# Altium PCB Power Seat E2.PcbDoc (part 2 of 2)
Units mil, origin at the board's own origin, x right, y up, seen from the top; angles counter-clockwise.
Board outline 6560 x 2560 mil, 2 copper layers (Top Layer, Bottom Layer), stack 61.4 mil thick; 98 components, 83 nets, 370 pads, 533 vias.
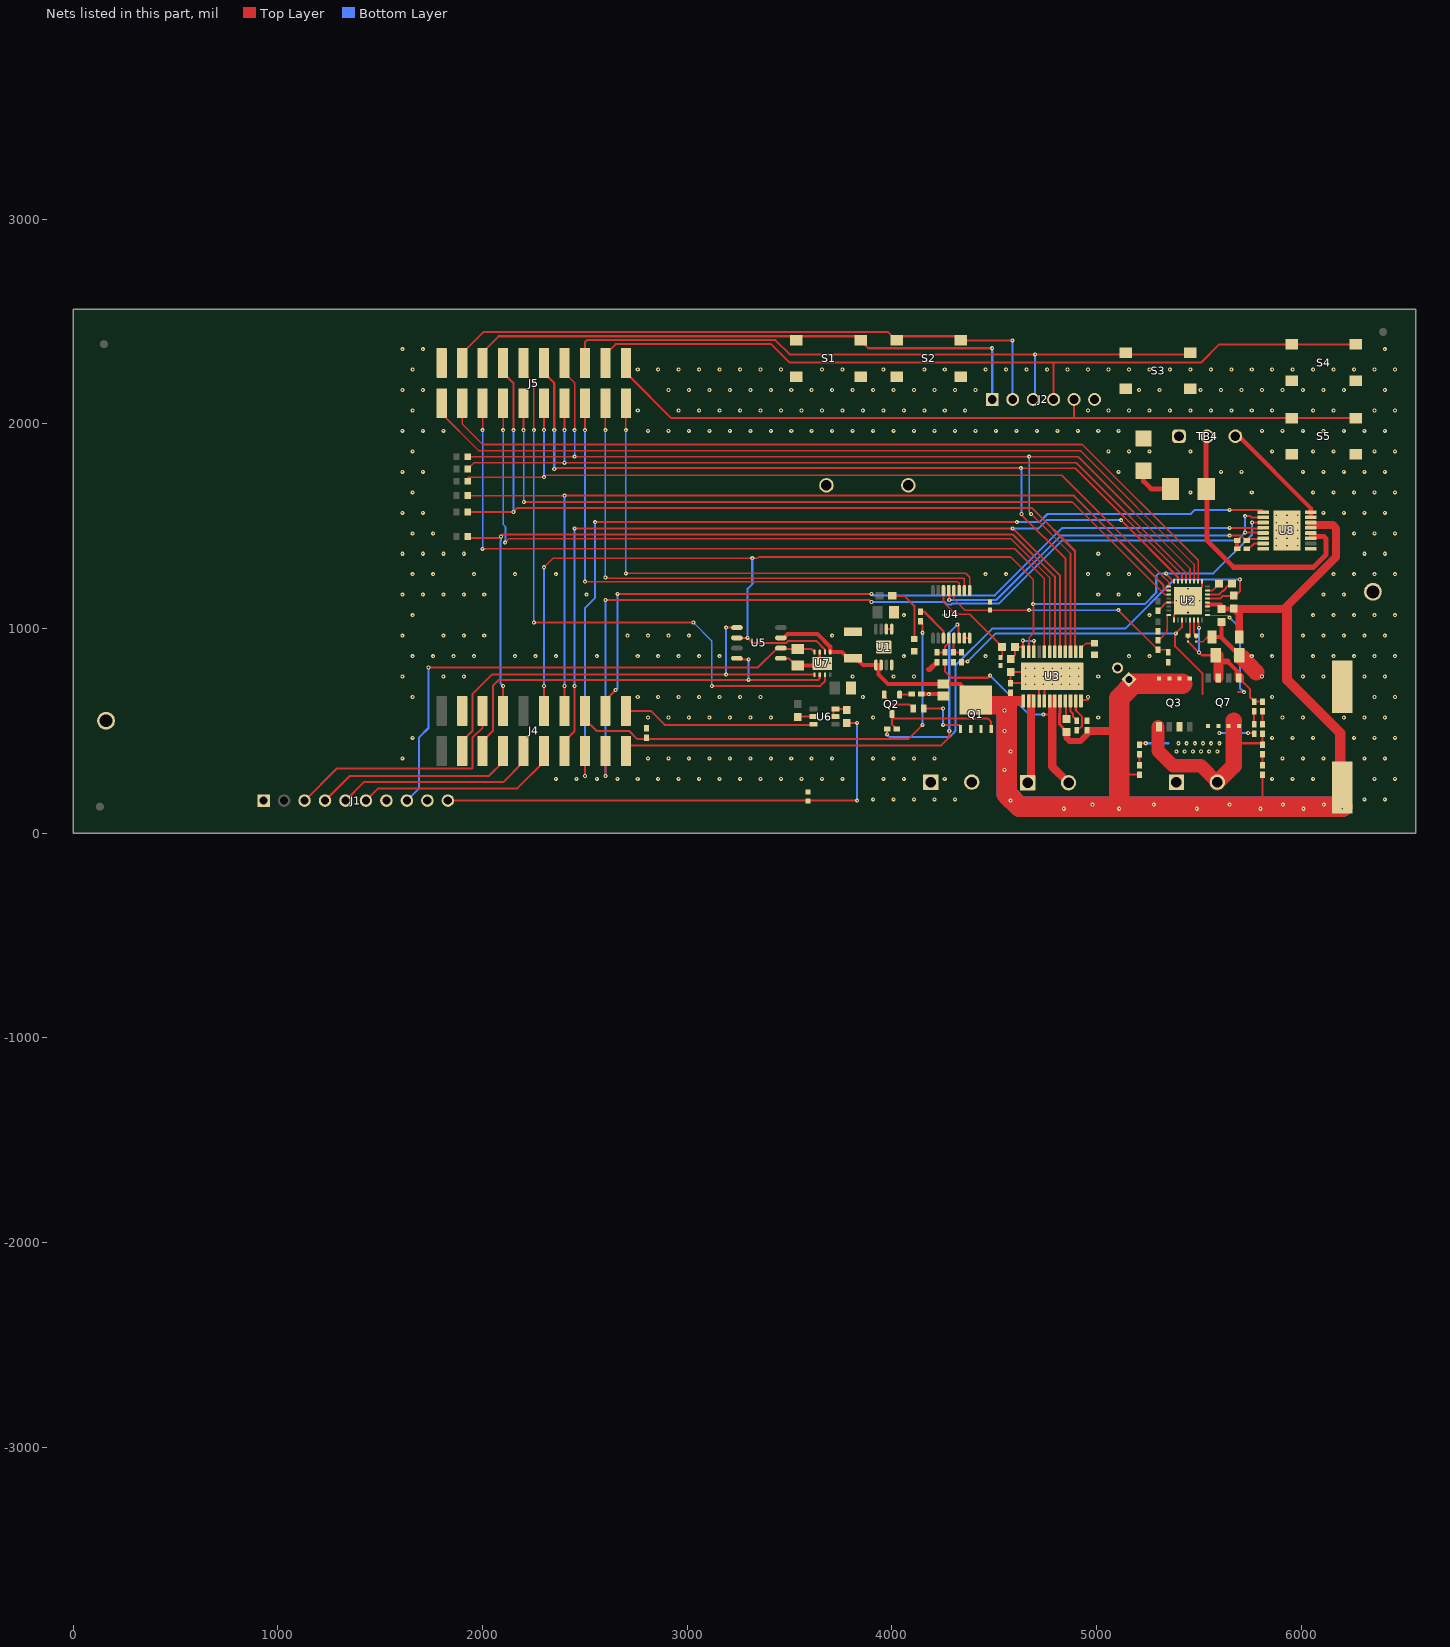
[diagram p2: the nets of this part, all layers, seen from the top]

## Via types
v1: diameter 19.68, hole 7.87, Top Layer to Bottom Layer, tented top, 364 vias
v2: diameter 19.68, hole 7.87, Top Layer to Bottom Layer, 148 vias
v3: diameter 19.68, hole 7.87, Top Layer to Bottom Layer, tented both sides, 21 vias

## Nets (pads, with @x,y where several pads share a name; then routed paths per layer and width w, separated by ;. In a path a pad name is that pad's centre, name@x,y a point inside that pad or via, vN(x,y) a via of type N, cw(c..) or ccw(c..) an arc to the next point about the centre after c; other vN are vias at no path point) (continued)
GND: C1.2 C2.2 C3.2 C4.2 C5.2 C6.2 C7.2 C8.2 C11.2 C12.2 C19.1 C20.2 C21.2 C23.1 C24.2 C25.2 C26.2 C27.2 D2.2 D3.2 D5.1 J1.1 J1.7 J1.9 J2.6 J4.4 J5.2 NT2.2 R2.1 R10.1 R13.1 R14.1 R19.1 R21.1 R22.2 R23.1 S1.1 S1.3 S2.1 S2.3 S3.1 S3.3 S4.1 S4.3 S5.1 S5.3 TB1.1 TB4.1 TP2.1 TP5.1 TP6.1 TP6.2 U1.4 U1.5 U1.6 U1.9 U2.1 U2.13 U2.17 U2.33 U3.16 U3.17 U3.24 U3.25@4783,767 U4.7 U4.8 U5.5 U6.2 U7.3 U7.9@3660,830 U8.8 U8.9 U8.17@5930,1480 | length 1951.5
  Top Layer w8: U2.17@5377.83,1042.24 5377.83,1067.83 5436.89,1126.89 v2(5446.73,1136.73) ; NT2.2@5486.73,936.73 5519.8,936.73 C11.2@5543.07,960
  Top Layer w10: U5.5@3457.28,855 3495,855 C23.1@3530,820 ; C24.2@3541.5,570 U6.2@3615.87,570 ; U7.9@3647.2,842.8 U7.3@3647.2,885.12 ; U1.6@3972.8,997.6 U1.5@3998.39,997.6 ; U4.7@4353.98,953.86 U4.8@4379.57,953.86 ; U3.16@4719.02,646.92 U3.25@4719.02,703.02 ; U3.17@4744.61,646.92 U3.25@4744.61,727.63 ; U3.25@4749.62,733.62 C20.2@4580,733.62 R14.1@4580,788.5 U3.25@4761.5,788.5 ; U3.24@4928.83,652 4958,652 v1(4958,666) ; C8.2@5300,1086.38 5327.56,1113.94 5327.56,1116.31 5336.25,1125 5338.62,1125 5340.51,1126.89 U2.13@5352.24,1126.89 U2.33@5436.89,1126.89 ; v2(5446.73,1136.73) 5515.63,1205.63 U2.1@5515.63,1231.22
  Top Layer w20: C23.1@3540,820 U7.9@3650,820 ; R2.1@4143.62,680 C5.2@4240.47,680 ; C11.2@5563.07,960 5607.09,960 ; 5610,962.91 C12.2@5610,1031.97 ; R23.1@5686.38,1390 R22.2@5686.38,1430
  Top Layer w25: 4180,800 4183.62,800 R21.1@4220,836.38 ; 5607.09,960 R13.1@5697.09,870
  Top Layer w80: R13.1@5710,860 5780,787.09
  other v1: 3908,166 4008,166 4108,166 4208,166 4308,166 6308,166 6408,166 2358,266 2458,266 2558,266 2658,266 2758,266 2858,266 2958,266 3058,266 3158,266 3258,266 3358,266 3458,266 3558,266 3658,266 3758,266 3958,266 4058,266 4258,266 5858,266 5958,266 6058,266 6358,266 6458,266 1608,366 2808,366 2908,366 3008,366 3108,366 3208,366 3308,366 3408,366 3508,366 3608,366 3708,366 3908,366 4008,366 4108,366 4208,366 5908,366 6008,366 6108,366 6308,366 6408,366 1658,466 5858,466 5958,466 6058,466 6258,466 6358,466 6458,466 2808,566 2908,566 3008,566 3108,566 3208,566 3308,566 3408,566 3908,566 5008,566 5908,566 6008,566 6208,566 6308,566 6408,566 1658,666 2758,666 2858,666 2958,666 3058,666 3158,666 3258,666 3358,666 3858,666 5858,666 6358,666 6458,666 1608,766 1808,766 1908,766 3808,766 4008,766 4108,766 5008,766 5808,766 6008,766 6108,766 6308,766 6408,766 1658,866 1758,866 1858,866 1958,866 2158,866 2258,866 2358,866 2558,866 2758,866 2858,866 2958,866 3058,866 3158,866 4058,866 4458,866 5158,866 5258,866 5758,866 5858,866 6058,866 6158,866 6258,866 6358,866 6458,866 1608,966 1808,966 1908,966 2008,966 2708,966 2808,966 2908,966 3008,966 3708,966 5808,966 6008,966 6108,966 6208,966 6308,966 6408,966 1658,1066 4058,1066 4258,1066 5258,1066 6058,1066 6158,1066 6258,1066 6358,1066 6458,1066 1608,1166 1708,1166 1808,1166 1908,1166 2008,1166 2508,1166 5008,1166 5108,1166 5208,1166 6108,1166 6208,1166 1658,1266 1758,1266 1958,1266 2158,1266 2358,1266 4458,1266 4558,1266 4958,1266 5058,1266 5158,1266 6158,1266 6258,1266 6358,1266 6458,1266 1608,1366 1708,1366 1808,1366 1908,1366 5008,1366 6308,1366 6408,1366 1658,1466 1758,1466 6258,1466 6358,1466 6458,1466 1608,1566 1708,1566 6108,1566 6208,1566 6308,1566 6408,1566 1658,1666 5458,1666 5758,1666 6058,1666 6158,1666 6258,1666 6358,1666 6458,1666 1608,1766 1708,1766 5108,1766 5608,1766 5708,1766 6008,1766 6108,1766 6208,1766 6308,1766 6408,1766 1658,1866 5058,1866 5158,1866 5258,1866 5458,1866 5858,1866 6058,1866 6158,1866 6358,1866 6458,1866 1608,1966 1708,1966 1808,1966 2808,1966 2908,1966 3008,1966 3108,1966 3208,1966 3308,1966 3408,1966 3508,1966 3608,1966 3708,1966 3808,1966 3908,1966 4008,1966 4108,1966 4208,1966 4308,1966 4408,1966 4508,1966 4608,1966 4708,1966 4808,1966 4908,1966 5008,1966 5108,1966 5808,1966 5908,1966 6008,1966 6108,1966 6208,1966 6308,1966 6408,1966 1658,2066 2758,2066 2958,2066 3058,2066 3158,2066 3258,2066 3358,2066 3458,2066 3558,2066 3658,2066 3758,2066 3858,2066 3958,2066 4058,2066 4158,2066 4258,2066 4358,2066 4958,2066 5058,2066 5158,2066 5258,2066 5358,2066 5458,2066 5558,2066 5658,2066 5758,2066 5858,2066 6058,2066 6158,2066 6358,2066 6458,2066 1608,2166 1708,2166 2908,2166 3008,2166 3108,2166 3208,2166 3308,2166 3408,2166 3508,2166 3608,2166 3708,2166 3808,2166 3908,2166 4008,2166 4108,2166 4208,2166 4308,2166 4408,2166 5208,2166 5308,2166 5508,2166 5608,2166 5708,2166 5808,2166 5908,2166 6008,2166 6108,2166 6208,2166 6408,2166 1658,2266 2758,2266 2858,2266 2958,2266 3058,2266 3158,2266 3258,2266 3358,2266 3458,2266 3658,2266 3758,2266 3958,2266 4158,2266 4258,2266 4458,2266 4558,2266 4658,2266 4758,2266 4858,2266 4958,2266 5058,2266 5158,2266 5258,2266 5358,2266 5458,2266 5558,2266 5658,2266 5758,2266 5858,2266 5958,2266 6058,2266 6158,2266 6258,2266 6358,2266 6458,2266 1608,2366 1708,2366 6408,2366
  other v2: 4180,680 4697.57,727.63 4739.69,727.63 4783,727.63 4826.31,727.63 4868.43,727.63 4697.57,767 4739.69,767 4783,767 4826.31,767 4868.43,767 4697.57,806.37 4739.69,806.37 4783,806.37 4826.31,806.37 4868.43,806.37 3660,808.35 3622.6,830 3697.4,830 3660,851.65 3936.38,892.28 3983.62,892.28 3960,910 3936.38,927.72 3983.62,927.72 5446.73,1078.66 5388.66,1136.73 5504.8,1136.73 5446.73,1194.8 5930,1442.6 5930,1480 5930,1517.4
  other v3: 4653.08,727.63 4912.92,727.63 4653.08,767 4912.92,767 4653.08,806.37 4912.92,806.37 5876.85,1405.2 5930,1405.2 5983.15,1405.2 5876.85,1442.6 5983.15,1442.6 5876.85,1480 5983.15,1480 5876.85,1517.4 5983.15,1517.4 5876.85,1554.8 5930,1554.8 5983.15,1554.8
Hall1: J1.3 J4.6 | length 1205
  Top Layer w10: J1.3@1150,160 J1.3@1130,160 1286.63,316.63 1946.63,316.63 1950,320 1950,466.54 2000,516.53 J4.6@2000,598
Hall2: J1.4 J4.7 | length 1000.7
  Top Layer w10: J1.4@1230,160 1350,280 2030,280 2100,350 J4.7@2100,402
Hall3: J1.5 J4.9 | length 1000.7
  Top Layer w10: J1.5@1330,160 1420,250 2100,250 2200,350 J4.9@2200,402
Hall4: J1.6 J4.11 | length 1000.7
  Top Layer w10: J1.6@1430,160 1490,220 2170,220 2300,350 J4.11@2300,402
HSS_FAULT: J4.18 U8.4 | length 3895.7
  Top Layer w10: J4.18@2600,598 2600,650 v2(2650,700) ; v2(2660,1170) v2(3900,1170) ; v1(5650,1492.72) 5759.41,1492.72 5762.13,1490 5811.06,1490 U8.4@5813.86,1492.8 U8.4@5813.86,1495.75
  Bottom Layer w10: v2(2650,700) 2660,710 v2(2660,1170) ; v2(3900,1170) 3907.28,1162.72 4502.72,1162.72 4830,1490 4832.72,1492.72 v1(5650,1492.72)
I_SENSE: C27.1 J4.16 R24.1 | length 2312
  Top Layer w10: J4.16@2500,640 J4.16@2500,598 2500,558.21 2558.21,500 2716.53,500 2756.53,460 4080,460 v1(4150,530) ; R24.1@4140,1036.38 4150,1026.38 v2(4150,980)
  Bottom Layer w10: v1(4150,530) v2(4150,980)
IN1_8703: J5.3 U2.2 | length 4066.6
  Top Layer w8: J5.3@1900,2102 1900,2000 2000,1900 4930,1900 5495.94,1334.05 U2.2@5495.94,1241.22
IN1_8873: J5.7 U3.7 | length 3797.6
  Top Layer w8: v2(2100,1970) J5.7@2100,2102 ; v2(2110,1420) 2130,1440 4580,1440 4770.2,1249.8 U3.7@4770.2,887.08
  Bottom Layer w8: v2(2100,1970) 2100,1510 2111.72,1498.28 2111.72,1421.72 v2(2110,1420)
IN2_8703: J5.1 U2.3 | length 4105.7
  Top Layer w8: J5.1@1800,2102 1800,2050 1980,1870 4920,1870 5476.26,1313.74 U2.3@5476.26,1241.22
IN2_8873: J5.5 U3.8 | length 3874.8
  Top Layer w8: v2(2000,1390) 4600,1390 4744.61,1245.39 U3.8@4744.61,887.08 ; v2(2000,1970) J5.5@2000,2102
  Bottom Layer w8: v2(2000,1390) v2(2000,1970)
Isense8703: C1.1 R5.2 R10.2 U4.12 | length 1196.8
  Top Layer w8: U4.12@4302.8,1186.14 4302.8,1144.6 4357.4,1090 v2(4670,1090) ; v2(5106.38,1090) R5.2@5300,896.38 5337.24,896.38 R10.2@5350,883.62
  Bottom Layer w8: v2(4670,1090) v2(5106.38,1090)
ISense8873: C2.1 R17.1 U4.14 | length 488.3
  Top Layer w8: U4.14@4251.61,1186.14 4251.61,1128.39 4310,1070 4380,1070 R17.1@4538.5,911.5 ; C2.1@4530,859.68 4538.5,868.19 R17.1@4538.5,910
IsenseHSS: R22.1 U4.13 U8.6 | length 1727.1
  Top Layer w10: v3(4280,1140) U4.13@4280,1183.35 ; v1(5650,1454.68) 5707.46,1454.68 5732.14,1430 R22.1@5733.62,1430 5733.62,1437.76 5810,1437.76 U8.6@5813.86,1441.61
  Bottom Layer w10: v3(4280,1140) 4510,1140 4824.69,1454.68 v1(5650,1454.68)
LED_HI: D3.1 J1.10 R15.2 | length 2410.3
  Top Layer w10: J1.10@1848.19,160 v2(3830,160) ; R15.2@3781.5,540 v2(3830,540)
  Bottom Layer w10: v2(3830,160) v2(3830,540)
LIGHT: J4.20 U6.3 | length 940.8
  Top Layer w10: J4.20@2700,598 2822,598 2890,530 U6.3@3610,530 ; U6.3@3604.01,530.42 U6.3@3605.87,532.28
LIN: C23.2 J1.8 U5.6 U7.4 | length 2622.6
  Top Layer w10: v2(1735.49,810) 3344.82,810 3439.82,905 U5.6@3457.28,905 ; U5.6@3460,900 C23.2@3540,900 3606.73,900 U7.4@3621.61,885.12
  Bottom Layer w10: J1.8@1630,160 1690,220 1690,469.02 1735.49,514.51 v2(1735.49,810)
Lumbar_Pump: D6.1 TB4.2 U8.11 U8.12 | length 1327.5
  Top Layer w25: D6.1@5535.01,1683.18 TB4.2@5535.01,1935.01 ; D6.1@5540,1678.19 5540,1430 5670,1300 6060,1300 6120,1360 6120,1440 6110,1450 6050.89,1450 6050.89,1458.82 U8.12@6046.14,1463.56
Lumbar_Valve: TB4.3 U8.15 U8.16 | length 557.9
  Top Layer w20: TB4.3@5677.8,1940 5694.8,1940 6045.24,1589.57 6046.14,1589.57 U8.16@6046.14,1569.57 U8.15@6046.14,1545.12
MODE: J5.9 U2.11 | length 3820.2
  Top Layer w8: v2(2200,1970) J5.9@2200,2102 ; v2(2201.39,1618.61) 4881.39,1618.61 5333.74,1166.26 U2.11@5352.24,1166.26
  Bottom Layer w8: v2(2201.39,1618.61) v2@2201.39,1968.61
MOTOR_CHECK_A: R18.1 R19.2 U4.5 | length 111.4
  Top Layer w10: U4.5@4302.8,953.86 4300,951.06 R19.2@4300,883.62 R18.1@4340,883.62
MOTOR_CHECK_B: R20.1 R21.2 U4.4 | length 117.4
  Top Layer w10: R21.2@4220,883.62 R20.1@4260,883.62 4260,912.81 4273.35,926.16 4273.35,950 U4.4@4277.2,953.86
MOTOR_OUT_1: R20.2 TB2.2 U3.18 U3.19 | length 1107.9
  Top Layer w10: R20.2@4260,836.38 4260,790 4290,760 4470,760 v2(4480,770) ; v1(4740,580) 4783,580 ; U3.19@4793,647 U3.19@4793.08,646.92
  Top Layer w40: 4783,657 4783,580 4783,327 TB2.2@4863,247
  Bottom Layer w10: v2(4480,770) 4670,580 v1(4740,580)
MOTOR_OUT_2: TB2.1 U3.14 U3.15 | length 438.3
  Top Layer w25: U3.14@4673,667 4683,667
  Top Layer w35: TB2.1@4663,247 TB2.1@4683,267
  Top Layer w40: TB2.1@4680,260 4680,660
MUX_INH: J4.19 U4.6 | length 2289
  Top Layer w10: J4.19@2700,402 2700,450 2720,430 4240,430 4280,470 v2(4280,500) ; v2(4320,1020) 4324.53,1015.47 4324.53,957.72 U4.6@4328.39,953.86
  Bottom Layer w10: v2(4280,500) 4280,980 v2(4320,1020)
MUXA: J5.15 U4.11 | length 2740.8
  Top Layer w8: v2(2500,1230) 2589.29,1230 2591,1228.28 2609,1228.28 2610.71,1230 4320,1230 4328.39,1221.61 U4.11@4328.39,1186.14 ; v2(2500,1970) J5.15@2500,2102
  Bottom Layer w8: v2(2500,1230) v2(2500,1970)
MUXB: J5.17 U4.10 | length 2667.5
  Top Layer w8: v2(2600,1250) 2610,1250 2613.98,1246.02 4353.98,1246.02 U4.10@4353.98,1186.14 ; v2(2600,1970) J5.17@2600,2102
  Bottom Layer w8: v2(2600,1250) v2(2600,1970)
MUXC: J5.19 U4.9 | length 2584
  Top Layer w8: v2(2700,1270) 2720,1270 4360,1270 4379.57,1250.43 U4.9@4379.57,1186.14 ; v2(2700,1970) J5.19@2700,2102
  Bottom Layer w8: v2(2700,1270) v2(2700,1970)
NetC9_2: C9.2 R3.2 | length 52.8
  Top Layer w10: C9.2@5810,333.62 R3.2@5810,386.38
NetC10_2: C10.2 R4.2 | length 52.8
  Top Layer w10: C10.2@5210,333.62 R4.2@5210,386.38
NetC14_1: C14.1 U2.30 | length 144.6
  Top Layer w10: U2.30@5541.22,1166.26 5597.76,1166.26 5616.73,1185.24 5620.33,1185.24 5631.06,1195.97 5631.06,1199.57 5651.5,1220 C14.1@5661.5,1220
NetC14_2: C14.2 U2.31 | length 71.4
  Top Layer w10: U2.31@5541.22,1185.95 5564.45,1185.95 C14.2@5598.5,1220
NetC15_2: C15.2 R6.2 | length 52.8
  Top Layer w10: C15.2@5810,543.62 R6.2@5810,596.38
NetC16_2: C16.2 R7.2 | length 52.8
  Top Layer w10: C16.2@5770,543.62 R7.2@5770,596.38
NetC18_1: C18.1 U3.21 | length 86.7
  Top Layer w10: U3.21@4850.83,643.06 4850.83,558.5 C18.1@4853,558.5
NetC19_2: C19.2 U3.1 | length 92.8
  Top Layer w8: U3.1@4923.75,887.08 4930,893.33 4930,910 4947.56,927.56 C19.2@4990,927.56
NetC22_1: C22.1 U3.22 | length 108.9
  Top Layer w10: U3.22@4872.57,646.92 4872.57,595.52 4884.57,583.51 4884.57,569.05 C22.1@4903,550.62
NetC22_2: C22.2 U3.23 | length 169.4
  Top Layer w10: U3.23@4898.16,646.92 4898.16,601.23 4927.69,571.7 4927.69,522.32 4908.75,503.38 C22.2@4903,503.38
NetD1_2: D1.2 Q2.2 | length 175.4
  Top Layer w10: Q2.2@3962.6,677.24 3962.6,667.4 4000,630 4084.41,630 D1.2@4104.41,610
NetD2_1: D2.1 R9.2 | length 289.7
  Top Layer w10: R9.2@4001.5,1160 4060,1160 4110,1110 D2.1@4110,949.53
NetD5_2: D5.2 D6.2 | length 197.5
  Top Layer w25: D5.2@5230,1771.26 5230,1720 5266.82,1683.18 D6.2@5360.99,1683.18
NetQ2_1: Q2.1 R2.2 | length 56.2
  Top Layer w10: Q2.1@4037.4,677.24 R2.2@4093.62,677.24
NetR5_1: R5.1 U2.16 | length 143.1
  Top Layer w8: R5.1@5300,943.62 5303.62,943.62 5343.13,983.13 5343.13,992.58 5345.02,994.47 U2.16@5345.02,1066
NetR14_2: R14.2 R17.2 U3.10 U3.12 | length 262.9
  Top Layer w10: R14.2@4580,851.5 4601.5,872.99 R17.2@4601.5,910 U3.12@4640,910 ; U3.12@4640,889.33 U3.12@4640,910 ; v1(4640,942.13) U3.12@4640,910 ; U3.10@4693.43,887.08 v2(4693.43,940)
  Bottom Layer w10: v1@4642.13,940 v2(4693.43,940)
NetR15_1: R15.1 U6.5 U6.6 | length 87.4
  Top Layer w10: U6.5@3714.13,569.68 3714.13,607.09 R15.1@3764.09,607.09
NetR23_2: R23.2 U8.7 | length 91.4
  Top Layer w10: R23.2@5733.62,1390 5743.62,1390 5768.94,1415.32 5813.86,1415.32 U8.7@5813.86,1416.02
NetR24_2: R24.2 U4.3 | length 191
  Top Layer w10: R24.2@4140,1083.62 4156.38,1083.62 4251.61,988.39 U4.3@4251.61,953.86 U4.3@4247.76,957.72
nSCS_8703: J5.13 R25.1 U2.5 | length 4068
  Top Layer w8: R25.1@1927.56,1780 1957.56,1810 v2(2400,1810) 4900,1810 5436.89,1273.11 U2.5@5436.89,1241.22 ; v2(2400,1970) J5.13@2400,2102
  Bottom Layer w8: v2(2400,1810) v2(2400,1970)
nSCS_8873: J4.8 R26.2 U3.6 | length 4192.6
  Top Layer w10: R26.2@1927.56,1450 1927.56,1443.28 2083.28,1443.28 v2(2090,1450) 2100,1460 4590,1460 4795.8,1254.2 U3.6@4795.8,887.08 ; J4.8@2100,598 v2(2100,720)
  Bottom Layer w10: v2(2090,1450) 2090,1432.13 2087.28,1429.41 2087.28,732.72 v2(2100,720)
nSLEEP: J4.12 U2.8 U3.11 U5.2 U7.2 U8.3 | length 5824
  Top Layer w8: J4.12@2300,598 v2(2300,720) ; v2(2300,1300) 2344.82,1344.82 v2(3317.42,1344.82) 3344.82,1344.82 3350,1350 4580,1350 4690,1240 v2(4690,1120) 4691.72,1118.28 4691.72,977.69 4671.72,957.69 4671.72,941.72 4670,940
  Top Layer w10: U5.2@3242.72,955 v2(3295,955) 3320,930 3483.93,930 3493.93,940 3630,940 3672.8,897.2 U7.2@3672.8,885.12 ; U3.11@4670,889.24 4670,940 ; v2(5340,1270) 5340,1266.61 5376.61,1230 U2.8@5377.83,1231.22 ; v2(5760,1518.39) U8.3@5813.86,1518.39 U8.3@5813.86,1520.43
  Bottom Layer w8: v2(2300,720) v2(2300,1300)
  Bottom Layer w10: v2(3295,955) 3295,1195 3320,1220 3317.42,1222.58 v2(3317.42,1344.82) ; v2(4690,1120) 5234.72,1120 5291.26,1176.54 5291.26,1257.87 5303.39,1270 v2(5340,1270) 5570,1270 5760,1460 v2(5760,1518.39)
OK_8703: J4.14 R11.2 U2.10 | length 4667.2
  Top Layer w8: R11.2@1927.56,1650 v2(2400,1650) ; J4.14@2400,608 v2(2400,720)
  Top Layer w10: v2(2400,1650) 4888.19,1650 5327.56,1210.63 5327.56,1196.53 5336.25,1187.83 5350.35,1187.83 U2.10@5352.24,1185.95
  Bottom Layer w8: v2(2400,720) v2(2400,1650)
OK_8873: J5.8 R16.2 U3.2 | length 4266.9
  Top Layer w10: R16.2@1927.56,1570 v2(2150,1570) 2170,1590 4683.64,1590 4894.3,1379.34 4894.3,890.94 U3.2@4898.16,887.08 ; J5.8@2100,2260 2100,2250 2150,2200 v2(2150,1970)
  Bottom Layer w10: v2(2150,1570) v2(2150,1970)
Pump_ON: J4.17 U8.2 U8.5 | length 4519.4
  Top Layer w10: v2(2600,280) J4.17@2600,402 ; v2(2600,1140) 3890,1140 v2(3900,1130) ; v1(5725.54,1470) U8.5@5811.06,1470 ; v2(5725.54,1550) 5750,1550 5756.02,1543.98 U8.2@5813.86,1543.98
  Bottom Layer w10: v2(2600,280) v2(2600,1140) ; v2(3900,1130) 4257.87,1130 4270.59,1117.28 4289.41,1117.28 4294.25,1122.13 4522.13,1122.13 4830,1430 5685.54,1430 v1(5725.54,1470) 5725.54,1525.54 v2(5725.54,1550)
RBG: Q1.4 Q2.3 R1.1 | length 609.2
  Top Layer w10: 4000,560 4470,560 4485,545 Q1.4@4485,509.57 ; Q2.3@4000,582.76 4000,533.62 R1.1@4023.62,510
RESET: J5.10 U7.7 | length 2962.3
  Top Layer w8: J5.10@2200,2250 2250,2200 v2(2250,1970) ; v2(2250,1030) v2(3030,1030)
  Top Layer w10: v2(3120,720) 3650,720 3672.8,742.8 U7.7@3672.8,774.88
  Bottom Layer w8: v2(2250,1030) v2(2250,1970) ; v2(3030,1030) 3120,940 v2(3120,720)
RXD: J4.3 U5.1 U7.5 | length 2272.5
  Top Layer w10: J4.3@1900,402 1900,450 1950,500 1950,680 2044.88,774.88 v1(3190,774.88) U7.5@3621.61,774.88 ; v1(3190,1005) U5.1@3222.72,1005
  Bottom Layer w10: v1(3190,774.88) v1(3190,1005)
S_N: C17.2 NT2.1 U2.22 | length 79.7
  Top Layer w10: U2.22@5476.26,1042.24 5476.26,977.2 5486.42,967.05 C17.2@5486.42,966.73
S_P: C17.1 NT1.2 U2.21 | length 66
  Top Layer w10: C17.1@5456.57,976.26 U2.21@5456.57,1042.24
SCLK: J4.13 U2.7 U3.5 | length 4907.4
  Top Layer w10: J4.13@2400,402 2400,450 2450,500 v2(2450,720) ; v2(2450,1490) v2(4590,1490) 4821.39,1258.61 U3.5@4821.39,887.08 ; v2(5119.42,1530) 5397.52,1251.9 U2.7@5397.52,1231.22
  Bottom Layer w10: v2(2450,720) v2(2450,1490) ; v2(4590,1490) 4716.36,1490 4756.36,1530 v2(5119.42,1530)
SDI: J5.12 U2.6 U3.4 | length 4845.3
  Top Layer w8: v2(4630,1784.38) 4895.62,1784.38 5128.28,1551.72 5128.42,1551.72 5141.14,1539 5141.14,1538.86 5417.2,1262.8 U2.6@5417.2,1231.22
  Top Layer w10: J5.12@2300,2298 2300,2250 2350,2200 v2(2350,1970) ; v2(2350,1780) 2354.38,1784.38 v2(4630,1784.38) ; v2(4632.72,1560) 4632.72,1557.28 4846.98,1343.02 U3.4@4846.98,887.08
  Bottom Layer w10: v2(2350,1780) v2(2350,1970) ; v2(4630,1784.38) 4632.72,1781.66 v2(4632.72,1560) v2@4635.43,1560
SDO: J5.14 R12.1 U2.4 U3.3 | length 5320.7
  Top Layer w8: R12.1@1930,1840 v2(2450,1840) v2(4670,1840) 4910,1840 5456.57,1293.43 U2.4@5456.57,1241.22 ; J5.14@2400,2298 2400,2250 2450,2200 v2(2450,1970) ; v2(4680,1560) 4872.57,1367.43 U3.3@4872.57,887.08
  Bottom Layer w8: v2(2450,1840) v2(2450,1970) ; v2(4670,1840) 4670,1570 v2(4680,1560)
SH1: C16.1 Q3.3 Q7.5 Q7.6 R4.1 R18.2 TB3.1 U2.19 | length 1839.7
  Top Layer w10: R18.2@4343.62,840 v2(4370,840) ; R4.1@5216.38,440 v3(5240,440) ; U2.19@5417.2,1042.24 5416.73,1041.77 5416.73,1006.73 v2(5386.73,976.73) 5384.02,974.02 5384.02,914.02 5518.35,779.69 5518.35,681.65 ; v1(5740,490) C16.1@5766.38,490
  Top Layer w50: TB3.1@5390,250 TB3.1@5390,260
  Bottom Layer w10: v2(4370,840) 4506.73,976.73 v2(5386.73,976.73) ; v3(5240,440) 5350,440 ; v1(5600,490) 5711.97,490 v1(5740,490)
  other v2: 5390,400 5430,400 5470,400 5510,400 5550,400 5590,400 5400,440 5440,440 5480,440 5520,440 5560,440 5600,440
SH2: C15.1 Q3.1 Q7.7 Q7.8 R3.1 TB3.2 U2.25 | length 1533.3
  Top Layer w6: U2.25@5541.22,1067.83 5541.22,1066.02 5583.36,1066.02 5584.98,1064.4 5639.06,1064.4 v1(5650,1053.46)
  Top Layer w10: 5670,440 5803.62,440 R3.1@5810,433.62 C15.1@5810,486.38 ; 5690,690 v1(5720,690)
  Top Layer w65: Q3.1@5300,520 5300,403.94 5375,328.94 ; 5380,330 5510,330 TB3.2@5590,250
  Top Layer w80: TB3.2@5590,250 5670,330 5670,440 5670,551.26
  Bottom Layer w10: v1(5650,1053.46) 5700,1003.46 5700,710 v1(5720,690)
SL2: NT1.1 Q7.1 Q7.3 R6.1 R7.1 R13.2 U2.23 | length 821.7
  Top Layer w10: NT1.1@5446.73,936.73 v2(5500,883.46) 5513.46,870 R13.2@5582.91,870 ; U2.23@5495.94,1042.24 5495.94,1036.65 5497.83,1034.76 5497.83,1005.63 v2(5500,1003.46) ; Q7.1@5695,758.94 5750,703.94 5750,663.62 R7.1@5770,643.62 R6.1@5810,643.62
  Top Layer w12: 5680,750 5680,784.85
  Top Layer w20: 5639.2,840 5710,769.2 5710,750
  Top Layer w30: R13.2@5595,840 5639.2,840
  Top Layer w50: Q7.3@5595,758.94 5595,840 R13.2@5595,871.61
  Bottom Layer w10: v2(5500,883.46) v2(5500,1003.46)
Switch1: J2.1 J5.6 S1.2 S1.4 | length 2830.5
  Top Layer w10: J5.6@2000,2298 2010,2308 2010,2360 2078.58,2428.58 S1.2@3846.5,2428.58 ; S1.2@3846.5,2408.58 3885.08,2370 v2(4490,2370)
  Bottom Layer w10: J2.1@4490,2120 4490,2360
Switch2: J2.2 J5.4 S2.2 S2.4 | length 3077.1
  Top Layer w10: J5.4@1900,2298 1900,2345 2005,2450 3980,2450 4001.42,2428.58 S2.2@4336.5,2428.58 ; S2.2@4336.5,2408.58 v2(4588.58,2408.58) v2@4590,2410
  Bottom Layer w10: J2.2@4588.58,2121.42 v2(4588.58,2408.58)
Switch3: J2.3 J5.16 S3.2 S3.4 | length 3307.2
  Top Layer w10: J5.16@2500,2298 2500,2400 2510,2410 3430,2410 3500,2340 v2(4700,2340) S3.2@5447.91,2340
  Bottom Layer w10: J2.3@4690,2120 4700,2130 v2(4700,2340)
Switch4: J2.4 J5.18 S4.2 S4.4 | length 3941.2
  Top Layer w10: J5.18@2600,2340 2650,2390 3410,2390 3500,2300 4790,2300 ; J2.4@4790,2120 4790,2300 ; S4.2@6266.5,2388.58 S4.4@5953.5,2388.58 5598.58,2388.58 5510,2300 4790,2300
Switch5: J2.5 J5.20 S5.2 S5.4 | length 3796.2
  Top Layer w10: J5.20@2700,2298 2720,2278 2720,2230.01 2920.01,2030 4890,2030 ; J2.5@4890,2120 4890,2030 ; S5.2@6266.5,2028.58 S5.4@5953.5,2028.58 5952.09,2030 4890,2030
TXD: J4.5 U5.4 U7.6 | length 2128.6
  Top Layer w10: J4.5@2000,402 2000,450 2050,500 2050,720 2080,750 3640,750 3647.2,757.2 U7.6@3647.2,774.88 ; U5.4@3242.72,855 3247.72,850 v2(3300,850)
  Bottom Layer w10: v2(3300,749.74) v2(3300,850)
Valve_OPEN: J4.15 U8.1 | length 4677.6
  Top Layer w10: v2(2500,280) J4.15@2500,402 ; v2(2550,1520) v2(4610,1520) ; v2(5650,1580) 5806.57,1580 5813.86,1572.72 U8.1@5813.86,1569.57
  Bottom Layer w10: v2(2500,280) 2500,1100 2550,1150 v2(2550,1520) ; v2(4610,1520) 4720,1520 4760,1560 5460,1560 5472.72,1572.72 5480,1580 v2(5650,1580)
VBATT: D1.1 Q1.1 Q1.2 Q1.3 TB1.2 | length 254.4
  Top Layer w10: D1.1@4155.59,610 v1(4250,610) ; v2(4250,530) 4330,530
  Bottom Layer w10: v2(4250,530) v1(4250,610)
VCP: C13.1 R1.2 U2.29 | length 2514
  Top Layer w10: v1@3976.38,483.62 v1(3976.81,483.19) R1.2@3976.81,509.57 ; U2.29@5541.22,1146.57 5543.03,1148.39 5605.16,1148.39 5616.77,1160 C13.1@5678.5,1160 ; C13.1@5665.08,1146.57 C13.1@5678.5,1160 ; v1(5700,1240) 5700,1181.5 C13.1@5678.5,1160
  Bottom Layer w10: v1(3976.81,483.19) 3990,470 4282.13,470 4302.72,490.59 4302.72,492.72 4310,500 4310,820 4490,1000 5140,1000 5380,1240 v1(5700,1240)
VIN+: C4.1 C5.1 C6.1 C9.1 C10.1 C11.1 C12.1 C13.2 C18.2 C20.1 C21.1 C26.1 Q1.5 Q3.5 Q3.6 Q3.7 Q3.8 U1.1 U1.2 U2.27 U2.28 U3.13 U3.20 U5.7 U7.1 U8.13 U8.14 | length 9458.9
  Top Layer w10: 5116.38,286.38 C10.1@5210,286.38 ; U2.27@5541.22,1107.2 U2.28@5541.22,1126.89 ; 5810,130 C9.1@5810,286.38
  Top Layer w15: U3.20@4821.39,646.92 4821.39,587.01 4818.93,584.55 4818.93,532.44 C18.2@4853,495.5
  Top Layer w20: U5.7@3472.13,955 3490,972.87 3637.13,972.87 3698.39,911.61 U7.1@3698.39,885.12 3754.88,885.12 3784.96,855.04 C4.1@3810,855.04 ; C4.1@3824.96,845.04 3834.96,845.04 3857.6,822.4 U1.1@3921.61,822.4 3933.84,822.4 3933.84,776.16 3980.47,729.53 C5.1@4250,729.53 4332.17,729.53 Q1.5@4410,651.69 ; 5541.22,1118.17 5606.73,1118.17
  Top Layer w25: C12.1@5606.73,1098.23 5609.72,1095.24 5666.73,1095.24 5690,1071.97 5690,1056.2 5690.22,1055.98 C11.1@5690,950 ; 5690,1030.73 5690.22,1030.95
  Top Layer w30: C18.2@4853,495.5 4853,467 4868.28,451.72 4921.72,451.72 C21.1@4960,490 ; C11.1@5700,950 5700,1080
  Top Layer w39.37: C13.2@5666.73,1095.24 5930,1095.24 ; 5915.24,1095.24 6170,1350 6170,1490 6154.41,1505.59 6046.14,1505.59
  Top Layer w40: 4966.38,500 5110,500
  Top Layer w50: Q1.5@4433.08,646.92 4625,646.92 ; 5930,1095.24 5930,750 6190,490 6190,233.94 C6.1@6200,223.94
  Top Layer w80: Q1.5@4430,620 4548.31,620
  Top Layer w100: 4560,620 4560,190 ; 4564.25,190 4560,190 ; 4624.25,130 4560,190 ; 4630,130 5810,130 C6.1@6200,130 ; 5110,140 5110,500 5110,660 5180,730 5417.52,730
  Bottom Layer w100: 4560,600 4560,194.25 4624.25,130 6200,130
  other v1: 5280,140
  other v2: 4840,120 5110,120 5490,120 5800,120 6010,120 6200,120 4980,140 5650,140 5910,140 6110,140 4580,160 4550,310 4580,400 4550,500 4550,600
WDFLT: J5.11 R8.1 U2.9 | length 4029.7
  Top Layer w8: 1927.56,1740 v2(2300,1740) 2310,1750 4830,1750 5318.28,1261.72 5318.28,1261 5331,1248.28 5331.72,1248.28 5352.24,1227.76 U2.9@5352.24,1205.63 ; v2(2300,1970) J5.11@2300,2102
  Bottom Layer w8: v2(2300,1740) v2(2300,1970)
pads on no net: FID1.1 FID2.1 FID3.1 J4.2 LBL1.0 U1.3 U1.7 U2. U2.32 U3.25@4783,767 U4.1 U4.2 U4.15 U5.3 U5.8 U6.4 U7.9@3635,830 U7.9@3685,830 U8.10 U8.17@5930,1480

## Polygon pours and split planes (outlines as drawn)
GND on Top Layer "Top Layer-GND" (solid, remove dead copper, pour order 4): 30.26,30.26 30.26,2532.74 6532.74,2532.74 6532.74,30.26
GND on Bottom Layer "Bottom GND" (solid, remove dead copper, pour order 2): 30.26,30.26 30.26,2532.74 6532.74,2532.74 6532.74,30.26

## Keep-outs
Keep-Out Layer:
  lines w10: 0,0 6563,0 6563,2563 0,2563 0,0
  lines w12: 755,-3730 3055,-3730
  text ".Layer_Name" at 577,-858.49 h60

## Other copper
Top Layer:
  rectangle net VBATT: 4320,190 4460,540
  region net SH1: 5510,720 5510,500 5500,490 5430,490 5430,538.63 5428.63,540 5390,540 5380,530 5380,390 5390,380 5610,380 5610,710 5600,720
  text ".Layer_Name" at 577,-858.49 h60
Bottom Layer:
  region net SH1: 5340,200 5490,200 5490,340 5500,350 5620,350 5620,450 5610,460 5350,460 5340,450
  text ".Layer_Name" at 577,-858.49 h60

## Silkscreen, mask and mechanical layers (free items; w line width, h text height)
Top Overlay:
  region: 110,1780 110,1480 210,1480 210,1780
  lines w5: 4510.31,469.68 4510.31,959.68 5019.69,959.68 5019.69,470.32 ; 4510.63,470 5020,470 ; 5280,490 5730,490 5730,1250 5280,1250 5280,490
  lines w10: 300,205 3200,205 ; 300,2500 3200,2500 3200,200 ; 302,200 302,2500
  text "'.PRJ_Number'.PCB_Rev-" at 190,750 h108.27 r90
  text "GND" at 4070,200 h60 r90
  text "GND" at 740,110 h60
  text ".Layer_Name" at 577,-858.49 h60
Bottom Overlay:
  text ".Layer_Name" at 577,-858.49 h60
Top Paste:
  text ".Layer_Name" at 577,-858.49 h60
Bottom Paste:
  text ".Layer_Name" at 577,-858.49 h60
Top Solder:
  text ".Layer_Name" at 577,-858.49 h60
  text ".Layer_Name" at 577,-858.49 h60
Bottom Solder:
  text ".Layer_Name" at 577,-858.49 h60
Drill Guide:
  text ".Layer_Name" at 577,-858.49 h60
M1 Board Outline:
  the board outline again, w10
  text ".Layer_Name" at 577,-858.49 h60
M2 Board Dimensions:
  rectangle: 0,-275 125,-150
  rectangle: 125,-400 500,-275
  lines w7: 0,-275 1000,-275 ; 125,-400 125,-150 ; 250,-400 250,-150 ; 500,-400 500,-150 ; 750,-400 750,-150 ; 0,-400 1000,-400 1000,-150 0,-150 0,-400
  text ".Layer_Name" at 577,-858.49 h60
M3 3D STEP Top:
  text ".Layer_Name" at 577,-858.49 h60
M4 3D STEP Bottom:
  text ".Layer_Name" at 577,-858.49 h60
M5 Assembly Top:
  lines w10: -292,-930.17 6308,-930.17 ; -292,-726.83 6310,-726.83 ; -292,-523.5 -292,-1133.5 3713,-1133.5 6310,-1133.5 6310,-523.5 -291.5,-523.5 -291.5,-1133.5 1284,-1133.5 ; 2173,-1133.5 2173,-523.5 ; 3440,-726.83 3440,-523.5 ; 4280,-726.83 4280,-523.5 ; 4902,-1140 4902,-937.17
  text "COMPONENTS MARKED 'DNP' SHOULD NOT BE POPULATED." at 1153.5,-318.5 h60
  text "ASSEMBLY VARIANT:" at 1153,-434 h60
  text ".VariantName" at 2189,-434 h60
  text "PCB VIEWED FROM TOP SIDE" at -228.5,-655.67 h60
  text "BOARD #:" at 2248,-655.67 h60
  text ".PRJ_Number" at 2793.5,-655.67 h60
  text "REV:" at 3638,-655.67 h60
  text ".PCB_Rev" at 3929.5,-655.67 h60
  text "SVN REV:" at 4476,-655.67 h60
  text ".VersionControl_RevNumber" at 4982,-655.67 h60
  text "TID #:" at 2248,-859 h60
  text ".TID" at 2793.5,-859 h60
  text "PLOT NAME =" at -228.5,-1064.34 h60
  text ".plot_File_Name" at 577,-1064.34 h60
  text "GENERATED    :" at 2250,-1064.34 h60
  text ".Print_Date" at 3119.5,-1064.34 h60
  text ".Print_Time" at 3848.5,-1064.34 h60
  text "TEXAS INSTRUMENTS" at 5113,-1064.34 h60
M6 Assembly Bottom:
  lines w10: -292.5,-727.33 6309.5,-727.33 ; -290.5,-930.67 6309.5,-930.67 ; 1115.5,-1140.5 1115.5,-937.67 ; 1737.5,-727.33 1737.5,-524 ; 2577.5,-727.33 2577.5,-524 ; 3844.5,-1134 3844.5,-524 ; 4733.5,-1134 6309,-1134 6309,-524 -292.5,-524 -292.5,-1134 2304.5,-1134 6309.5,-1134 6309.5,-524
  text "COMPONENTS MARKED 'DNP' SHOULD NOT BE POPULATED." at 6102,-318 h60
  text ".VariantName" at 5058,-434 h60
  text "ASSEMBLY VARIANT:" at 6097,-434 h60
  text ".VersionControl_RevNumber" at 1035.5,-656.17 h60
  text "SVN REV:" at 1541.5,-656.17 h60
  text ".PCB_Rev" at 2088,-656.17 h60
  text "REV:" at 2379.5,-656.17 h60
  text ".PRJ_Number" at 3224,-656.17 h60
  text "BOARD #:" at 3769.5,-656.17 h60
  text "PCB VIEWED FROM BOTTOM SIDE" at 6246,-656.17 h60
  text ".TID" at 3224,-859.5 h60
  text "TID #:" at 3769.5,-859.5 h60
  text "TEXAS INSTRUMENTS" at 904.5,-1064.84 h60
  text ".Print_Time" at 2169,-1064.84 h60
  text ".Print_Date" at 2898,-1064.84 h60
  text "GENERATED    :" at 3767.5,-1064.84 h60
  text ".plot_File_Name" at 5440.5,-1064.84 h60
  text "PLOT NAME =" at 6246,-1064.84 h60
M9 Title Sheet:
  drawing of 57 lines, arcs and shapes, not listed
  text "1" at 739.84,8036.5 h70
  text "2" at 3235.5,8036.5 h70
  text "3" at 5724.84,8036.5 h70
  text "4" at 8231.51,8036.5 h70
  text "5" at 10730.5,8036.5 h70
  text "6" at 13235.5,8036.5 h70
  text "A" at -416.5,6893.5 h70
  text "A" at 14383.5,6893.5 h70
  text "B" at -416.5,4513.5 h70
  text "B" at 14383.5,4513.5 h70
  text "C" at -416.5,2138.5 h70
  text "C" at 14383.5,2138.5 h70
  text "PROJECT TITLE:" at 11343.5,277.5 h45
  text ".PRJ_Title" at 11393.5,144.17 h70
  text "DESIGNED FOR:" at 11343.5,-23.5 h45
  text ".PRJ_Customer" at 11393.5,-163.5 h70
  text "D" at -416.5,-231.5 h70
  text "D" at 14383.5,-231.5 h70
  text "FILE NAME:" at 11343.5,-323.5 h45
  text ".PCB_File_Name_No_Path" at 11393.5,-443.5 h70
  text "Texas Instruments (TI) and/or its licensors do not warrant the accuracy or completeness of this specification" at 6374,-605.34 h45
  text "ENGINEER:" at 11343.5,-613.5 h45
  text "LAYOUT BY:" at 12848.5,-613.5 h45
  text "or any information contained therein. TI and/or its licensors do not warrant that this design will meet" at 6329.01,-718 h45
  text ".PRJ_Engineer" at 11393.5,-768.49 h70
  text ".PCB_Layout" at 12899,-768.49 h70
  text "the specifications, will be suitable for your application or fit for any particular purpose, or will operate in" at 6329.01,-830.67 h45
  text ".Layer_Name" at 577,-858.49 h60
  text "ALTIUM DESIGNER VERSION:" at 12848.5,-923.5 h45
  text "an implementation. TI and/or its licensors do not warrant that the design is production worthy. You should" at 6329.01,-943.33 h45
  text "completely validate and test your design implementation to confirm the system functionality for your application." at 6374,-1056 h45
  text ".print_Scale" at 11393.5,-1056.83 h70
  text ".Application_BuildNumber" at 12899,-1056.83 h70
  text "1" at 739.84,-1263.5 h70
  text "2" at 3235.5,-1263.5 h70
  text "3" at 5724.84,-1263.5 h70
  text "4" at 8231.51,-1263.5 h70
  text "5" at 10730.5,-1263.5 h70
  text "6" at 13235.5,-1263.5 h70
M10 Fab Notes:
  drawing of 173 lines, arcs and shapes, not listed
  text "DESIGN INFORMATION" at 12378.02,6201 h60
  text "MIN. TRACK WIDTH:" at 11733.46,6021 h60
  text "8" at 12829.7,6021 h60
  text "MIL" at 12984.46,6021 h60
  text "MIN. CLEARANCE:" at 11733.46,5889 h60
  text "0.2" at 12769.7,5889 h60
  text "mm" at 12984.46,5889 h60
  text "MIN. VIA PAD SIZE:" at 11733.46,5757 h60
  text "24" at 12799.71,5757 h60
  text "MIL" at 12984.46,5757 h60
  text "0.05mm (2MIL)" at 12428.46,5615.29 h60
  text "MINIMUM ANNULAR RING" at 11404.23,5611 h60
  text "EXTERNAL" at 13136.46,5611 h60
  text "PER" at 11604.23,5493 h60
  text "IPC-D-275 CLASS 2 LEVEL C" at 11824.23,5493 h60
  text "MIL, HOLES" at 13312.46,5380.71 h60
  text "+/-" at 12920,5380 h60
  text "+/-" at 13774,5380 h60
  text "REGISTRATION TOLERANCES:" at 11404.23,5375 h60
  text "METAL" at 12604,5375 h60
  text "5" at 13180.2,5375 h60
  text "3" at 14013.2,5375 h60
  text "MIL" at 14129.46,5375 h60
  text "+/-" at 13774,5262 h60
  text "HOLE SIZE TOLERANCE (UNLESS OTHERWISE SPECIFIED):" at 11404.23,5257 h60
  text "3" at 14013.2,5257 h60
  text "MIL" at 14129.46,5257 h60
  text "MATERIAL:" at 11329.46,5047.54 h60
  text "FR-4 High Tg" at 12315.9,4907.21 h60
  text "FR-408" at 11750.46,4898.64 h60
  text "OTHER" at 13238.46,4898.64 h60
  text "X" at 12161,4895 h60
  text "62 MIL (1.6mm) +/-10%" at 12070.56,4735.92 h60
  text "THICKNESS:" at 11404.23,4731.64 h60
  text "X" at 11942.4,4731.64 h60
  text "OTHER" at 13355.46,4731.64 h60
  text "TOLERANCE:" at 11404.23,4573.64 h60
  text "X" at 12243.53,4573.64 h60
  text "ANSI IPC-6012 TYPE 3 CLASS 2" at 12430.48,4573.64 h60
  text "OTHER +/-" at 12430.46,4417.64 h60
  text "BOW & TWIST:" at 11404.23,4260.64 h60
  text "X" at 12243.53,4260.64 h60
  text "ANSI IPC-6012 TYPE 3 CLASS 2" at 12430.48,4260.64 h60
  text "OTHER +/-" at 12430.46,4102.13 h60
  text "DRILLING:" at 11329.46,3963.64 h60
  text "REFERENCE:" at 11404.23,3846.64 h60
  text "X" at 12052.46,3846.64 h60
  text "AS SHOWN" at 12239.46,3846.64 h60
  text "X" at 12953.46,3846.64 h60
  text "NC_DRILL FILES" at 13090.46,3846.64 h60
  text "PTH COPPER THICKNESS:" at 11404.23,3688.64 h60
  text "X" at 12534.46,3688.64 h60
  text "20-30 um" at 12671.46,3688.64 h60
  text "OTHER" at 13388.46,3688.64 h60
  text "BOARD FINISH:" at 11329.46,3529.64 h60
  text "SILKSCREEN:" at 11484.68,3411.64 h60
  text "X" at 12433.46,3411.64 h60
  text "TOP" at 12559.46,3411.64 h60
  text "X" at 12943.46,3411.64 h60
  text "BOTTOM" at 13070.46,3411.64 h60
  text "SILKSCREEN COLOR:" at 11484.68,3244.64 h60
  text "X" at 12432.42,3244.64 h60
  text "WHITE" at 12559.46,3244.64 h60
  text "OTHER" at 13070.46,3244.64 h60
  text "GREEN" at 12690.46,3085.44 h60
  text "OTHER" at 13308.46,3085.44 h60
  text "SOLDER RESIST COLOR:" at 11484.68,3074.64 h60
  text "X" at 12563.42,2915.44 h60
  text "MATTE" at 12690.46,2915.44 h60
  text "SEMI-GLOSS" at 13308,2914.8 h60
  text "IMMERSION GOLD (ENIG)" at 12390.46,2726.92 h60
  text "ENEPIG" at 13728,2723.64 h60
  text "SURFACE FINISH:" at 11329.46,2722.64 h60
  text "X" at 12203.51,2722.64 h60
  text "IMM. TIN/SILVER OR EQUIV" at 11659,2565.64 h60
  text "OTHER" at 13090.46,2565.64 h60
  text "ARRAY/PANEL:" at 11329.46,2386.64 h60
  text "CUT AND TRIM PER M1 BOARD OUTLINE" at 12390.46,2382.35 h60
  text "N.C. ROUTE" at 12390.46,2230.64 h60
  text "X" at 13069.46,2230.64 h60
  text "V. SCORE" at 13256.46,2230.64 h60
  text "CERTIFICATION:" at 11329.46,2093.64 h60
  text "MATERIALS AND WORKMANSHIP FOR ALL PCBS" at 12054.46,2093.64 h60
  text "TO MEET OR EXCEED THE REQUIREMENTS OF:" at 12054.46,1995.64 h60
  text "X" at 11680.96,1859.13 h60
  text "ANSI IPC-A-600F CLASS ->" at 11819.96,1859.13 h60
  text "X" at 13459.02,1859.13 h60
  text "2" at 13577.96,1859.14 h60
  text "1" at 13262.96,1857.64 h60
  text "3" at 13931.96,1857.64 h60
  text "X" at 12495.02,1699.64 h60
  text "RoHS" at 12631.96,1699.64 h60
  text "OTHER" at 13276.36,1699.64 h60
  text "PER ORDER" at 13673.42,1699.64 h60
  text "ALL BOARDS MUST MEET OR EXCEED UL94-V0 REQUIREMENTS." at 11357,1534 h60
  text "PCB MUST BEAR THE UL94V-0 UL REGISTERED MATERIAL ID NUMBER" at 11357,1414 h60
  text "ADDITIONAL REQUIREMENTS:" at 11329.46,1240.64 h60
  text "MICROSECTION:" at 11404.23,1125.64 h60
  text "YES" at 12309.96,1125.64 h60
  text "REQUIRED" at 13171.46,969.49 h60
  text "BARE BOARD ELEC. TEST:" at 11404.23,966.64 h60
  text "NONE" at 12709.96,966.64 h60
  text "X" at 13044.46,966.64 h60
  text "PER ORDER" at 13763.46,966.64 h60
  text ".Layer_Name" at 577,-858.49 h60
M11 Gerber Information:
  lines w10: -292,-930.17 6308,-930.17 ; -292,-726.83 6310,-726.83 ; -292,-523.5 -292,-1133.5 3713,-1133.5 6310,-1133.5 6310,-523.5 -291.5,-523.5 -291.5,-1133.5 1284,-1133.5 ; 2173,-1133.5 2173,-523.5 ; 3440,-726.83 3440,-523.5 ; 4280,-726.83 4280,-523.5 ; 4902,-1140 4902,-937.17
  text "ALL ARTWORK VIEWED FROM TOP SIDE" at -228.5,-655.67 h60
  text "BOARD #:" at 2248,-655.67 h60
  text ".PRJ_Number" at 2793.5,-655.67 h60
  text "REV:" at 3638,-655.67 h60
  text ".PCB_Rev" at 3929.5,-655.67 h60
  text "SVN REV:" at 4476,-655.67 h60
  text ".VersionControl_RevNumber" at 4982,-655.67 h60
  text "LAYER NAME =" at -228.5,-858.49 h60
  text "TID #:" at 2248,-859 h60
  text ".TID" at 2793.5,-859 h60
  text "PLOT NAME =" at -228.5,-1064.34 h60
  text ".plot_File_Name" at 577,-1064.34 h60
  text "GENERATED    :" at 2250,-1064.34 h60
  text ".Print_Date" at 3119.5,-1064.34 h60
  text ".Print_Time" at 3848.5,-1064.34 h60
  text "TEXAS INSTRUMENTS" at 5113,-1064.34 h60
M12 Stackup:
  drawing of 339 lines, arcs and shapes, not listed
  text "Layer" at 8067.5,7830 h60
  text "Name" at 8477.41,7830 h60
  text "Material" at 9407.16,7830 h60
  text "Thickness" at 10266.92,7830 h60
  text "Constant" at 10916.76,7830 h60
  text "Board Layer Stack" at 11486.62,7830 h60
  text "Board Layer Stack" at 12606.3,7830 h60
  text "1" at 8067.5,7710 h60
  text "Top Overlay" at 8477.41,7710 h60
  text "2" at 8067.5,7590 h60
  text "Top Solder" at 8477.41,7590 h60
  text "Solder Resist" at 9407.16,7590 h60
  text "0.40mil" at 10266.92,7590 h60
  text "3.5" at 10916.76,7590 h60
  text "3" at 8067.5,7470 h60
  text "Top Layer" at 8477.41,7470 h60
  text "Copper" at 9407.16,7470 h60
  text "4.20mil" at 10266.92,7470 h60
  text "4" at 8067.5,7350 h60
  text "Dielectric1" at 8477.41,7350 h60
  text "FR-4" at 9407.16,7350 h60
  text "53.00mil" at 10266.92,7350 h60
  text "4.8" at 10916.76,7350 h60
  text "5" at 8067.5,7230 h60
  text "Bottom Layer" at 8477.41,7230 h60
  text "Copper" at 9407.16,7230 h60
  text "4.20mil" at 10266.92,7230 h60
  text "6" at 8067.5,7110 h60
  text "Bottom Solder" at 8477.41,7110 h60
  text "Solder Resist" at 9407.16,7110 h60
  text "0.40mil" at 10266.92,7110 h60
  text "3.5" at 10916.76,7110 h60
  text "7" at 8067.5,6990 h60
  text "Bottom Overlay" at 8477.41,6990 h60
  text ".Layer_Name" at 577,-858.49 h60
M13 Component Bodies Top:
  text ".Layer_Name" at 577,-858.49 h60
M14 Component Bodies Bottom:
  text ".Layer_Name" at 577,-858.49 h60
M15 Courtyards Top:
  text ".Layer_Name" at 577,-858.49 h60
M16 Courtyards Bottom:
  text ".Layer_Name" at 577,-858.49 h60
Drill Drawing:
  circle w10: c3363.73,3318.92 r27.63
  lines w10: 3336.1,3042.62 3391.36,3042.62 3391.36,3097.88 3336.1,3097.88 3336.1,3042.62 ; 3336.1,3222.22 3391.36,3222.22 3363.73,3166.95 3336.1,3222.22 ; 3336.1,3429.44 3349.91,3429.44 3363.73,3415.62 3377.54,3429.44 3391.36,3429.44 3377.54,3443.26 3391.36,3457.07 3377.54,3457.07 3363.73,3470.89 3349.91,3457.07 3336.1,3457.07 3349.91,3443.26 3336.1,3429.44 ; 3336.1,3539.96 3363.73,3553.78 3391.36,3539.96 3377.54,3567.59 3391.36,3595.22 3363.73,3581.41 3336.1,3595.22 3349.91,3567.59 3336.1,3539.96 ; 3336.1,3691.93 3363.73,3664.3 3391.36,3691.93 3363.73,3719.56 3336.1,3691.93 ; 3336.1,3802.45 3349.91,3802.45 3349.91,3788.63 3377.54,3788.63 3377.54,3802.45 3391.36,3802.45 3391.36,3830.08 3377.54,3830.08 3377.54,3843.89 3349.91,3843.89 3349.91,3830.08 3336.1,3830.08 3336.1,3802.45
  lines w12: 3286,3005.32 6516.06,3005.32 ; 3286,3875.66 6516.06,3875.66 ; 3623.75,2880.98 3623.75,4000 ; 3955.56,2880.98 3955.56,4000 ; 4591.66,2880.98 4591.66,4000 ; 4850.66,2880.98 4850.66,4000 ; 5225.64,2880.98 5225.64,4000 ; 5949.86,2880.98 5949.86,4000 ; 3286,2880.98 6516.06,2880.98 6516.06,4000 3286,4000 3286,2880.98
  text "Symbol" at 3360.6,3912.97 h72
  text "Quantity" at 3661.05,3912.97 h72
  text "Finished Hole Size" at 3992.86,3912.97 h72
  text "Plated" at 4628.96,3912.97 h72
  text "Hole Type" at 4887.96,3912.97 h72
  text "Drill Layer Pair" at 5262.94,3912.97 h72
  text "Hole Tolerance" at 5987.16,3912.97 h72
  text "533" at 3661.05,3788.63 h60
  text "7.87mil (0.200mm)" at 3992.86,3788.63 h60
  text "PTH" at 4628.96,3788.63 h60
  text "Round" at 4887.96,3788.63 h60
  text "Top Layer - Bottom Layer" at 5262.94,3788.63 h60
  text "2" at 3661.05,3664.3 h60
  text "33.47mil (0.850mm)" at 3992.86,3664.3 h60
  text "PTH" at 4628.96,3664.3 h60
  text "Round" at 4887.96,3664.3 h60
  text "Top Layer - Bottom Layer" at 5262.94,3664.3 h60
  text "10" at 3661.05,3539.96 h60
  text "40.16mil (1.020mm)" at 3992.86,3539.96 h60
  text "PTH" at 4628.96,3539.96 h60
  text "Round" at 4887.96,3539.96 h60
  text "Top Layer - Bottom Layer" at 5262.94,3539.96 h60
  text "6" at 3661.05,3415.62 h60
  text "43.31mil (1.100mm)" at 3992.86,3415.62 h60
  text "PTH" at 4628.96,3415.62 h60
  text "Round" at 4887.96,3415.62 h60
  text "Top Layer - Bottom Layer" at 5262.94,3415.62 h60
  text "3" at 3661.05,3291.29 h60
  text "47.24mil (1.200mm)" at 3992.86,3291.29 h60
  text "PTH" at 4628.96,3291.29 h60
  text "Round" at 4887.96,3291.29 h60
  text "Top Layer - Bottom Layer" at 5262.94,3291.29 h60
  text "8" at 3661.05,3166.95 h60
  text "51.18mil (1.300mm)" at 3992.86,3166.95 h60
  text "PTH" at 4628.96,3166.95 h60
  text "Round" at 4887.96,3166.95 h60
  text "Top Layer - Bottom Layer" at 5262.94,3166.95 h60
  text "2" at 3661.05,3042.62 h60
  text "63.00mil (1.600mm)" at 3992.86,3042.62 h60
  text "PTH" at 4628.96,3042.62 h60
  text "Round" at 4887.96,3042.62 h60
  text "Top Layer - Bottom Layer" at 5262.94,3042.62 h60
  text "564 Total" at 3661.05,2918.28 h60
  text ".Layer_Name" at 577,-858.49 h60
M17 Embedded Cavity:
  text ".Layer_Name" at 577,-858.49 h60
M18 Embedded Assembly:
  text ".Layer_Name" at 577,-858.49 h60
M19 Embedded Keepout:
  text ".Layer_Name" at 577,-858.49 h60

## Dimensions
0,-400 to 1000,-400 on M2 Board Dimensions
0,0 to 0,2560 on M2 Board Dimensions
